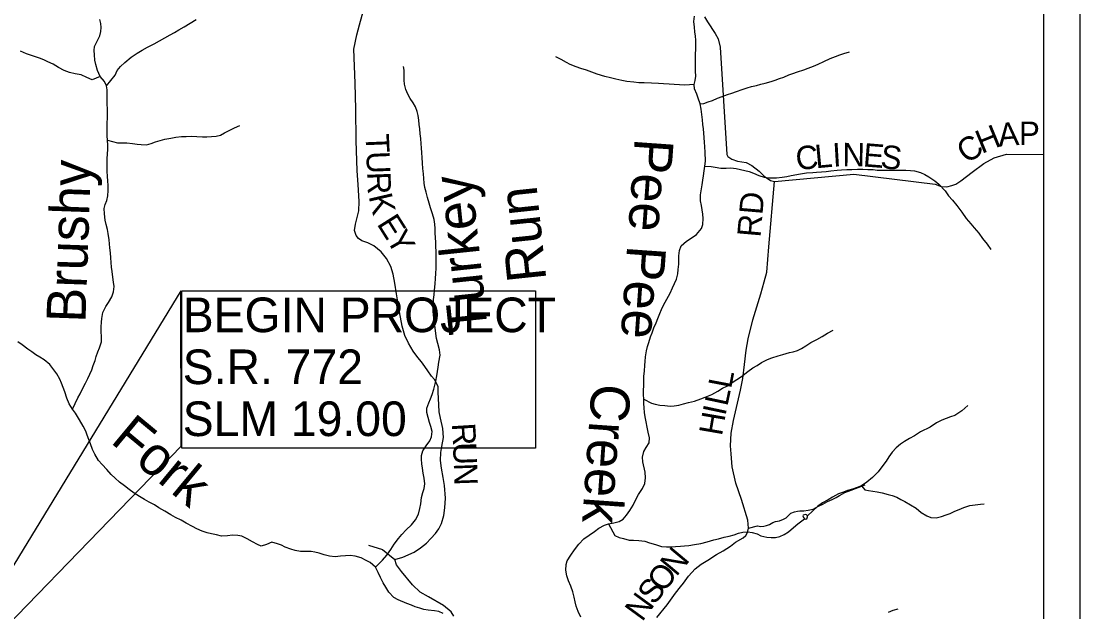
# Model space of a CAD drawing. Extents: x 0 to 34, y 0 to 22.
# Drawn here: x 6.52 to 9.087, y 16.76 to 18.193 of the extents above; entities that cross this region are included whole.
import ezdxf

# ---------------------------------------------------------------- set-up
doc = ezdxf.new("R2010")
doc.units = 0
for name, color, linetype in [('Default', 7, 'Continuous'), ('GM_X_County_Road', 7, 'Continuous'), ('GM_X_County_Road_Text', 7, 'Continuous'), ('GM_X_Minor_Lake', 7, 'Continuous'), ('GM_X_Minor_River', 7, 'Continuous'), ('GM_X_Minor_River_Text', 7, 'Continuous'), ('GM_X_Township_Road', 7, 'Continuous'), ('GM_X_Township_Road_Text', 7, 'Continuous'), ('SH_Cut_Line', 7, 'Continuous'), ('SH_Text', 7, 'Continuous')]:
    doc.layers.add(name, color=color, linetype=linetype)

msp = doc.modelspace()

# ---------------------------------------------------------------- linework, layer by layer
at = {"layer": 'Default'}
msp.add_lwpolyline([(9.087, 13.8822), (2.1062, 13.8822), (2.1062, 20.9054), (9.087, 20.9054)], close=True, dxfattribs=at)
msp.add_lwpolyline([(9, 14), (9, 18.8941), (8.8762, 18.9027), (8.0305, 18.9725), (6.8442, 19.0679), (6.226, 19.1161), (5.8337, 19.1499), (5.3224, 19.1939), (5.1554, 19.2083), (4.831, 19.2363), (4.7661, 18.9124), (5.0018, 18.1008), (4.9996, 18.0806), (4.937, 17.4953), (4.9239, 17.3511), (4.9207, 17.3435), (4.6758, 16.8903), (4.7194, 16.7424)], dxfattribs=at)
at = {"layer": 'GM_X_County_Road'}
for points in [[(8.177, 18.2034), (8.1838, 18.1912), (8.2026, 18.1634), (8.2098, 18.1501), (8.2151, 18.13), (8.2309, 17.8696), (8.2336, 17.8646), (8.243, 17.8585), (8.2571, 17.8532), (8.2779, 17.8497), (8.2916, 17.8425), (8.3097, 17.8291), (8.3215, 17.8173), (8.337, 17.8067), (8.3465, 17.8041), (8.5389, 17.822), (8.7365, 17.7975), (8.751, 17.7918), (8.7642, 17.7913), (8.7768, 17.7943), (8.7866, 17.7977), (8.7984, 17.8057), (8.8258, 17.8264), (8.8543, 17.8476), (8.8794, 17.8616), (8.9094, 17.8706), (9, 17.8699)], [(8.0612, 16.7466), (8.0867, 16.7772), (8.1065, 16.8053), (8.1184, 16.8206), (8.1256, 16.8299), (8.1381, 16.8465), (8.1541, 16.8643), (8.1686, 16.8761), (8.1846, 16.8855), (8.2059, 16.8995), (8.2218, 16.9085), (8.2397, 16.9195), (8.2519, 16.9289), (8.2709, 16.9395), (8.277, 16.9452), (8.2812, 16.9524), (8.2835, 16.9634), (8.282, 16.9824), (8.2662, 17.0329), (8.2531, 17.072), (8.2441, 17.1115), (8.2412, 17.1431), (8.2401, 17.1632), (8.2413, 17.1935), (8.2471, 17.2243), (8.2644, 17.2982), (8.2698, 17.3263), (8.2741, 17.3601), (8.278, 17.395), (8.283, 17.4227), (8.2942, 17.4682), (8.3134, 17.5312), (8.3214, 17.5607), (8.3283, 17.5842), (8.3331, 17.6453), (8.3465, 17.8041)]]:
    msp.add_lwpolyline(points, dxfattribs=at)
at = {"layer": 'GM_X_Minor_Lake'}
for points in [[(8.4245, 16.9957), (8.4222, 16.996), (8.4196, 16.9956), (8.4165, 16.9948), (8.415, 16.9933), (8.4166, 16.9892), (8.4193, 16.9854), (8.4227, 16.9847), (8.4254, 16.9858), (8.4268, 16.9904), (8.4269, 16.9934)], [(8.4269, 16.9934), (8.4245, 16.9957)]]:
    msp.add_lwpolyline(points, dxfattribs=at)
at = {"layer": 'GM_X_Minor_River'}
for points in [[(8.1132, 17.5902), (8.1143, 17.6035), (8.1142, 17.6134), (8.1145, 17.6236), (8.1166, 17.6369), (8.1199, 17.648), (8.1328, 17.6595), (8.1448, 17.6668), (8.1573, 17.6757), (8.1693, 17.6898), (8.1727, 17.6993), (8.1737, 17.7142), (8.1732, 17.7248), (8.1712, 17.735), (8.1692, 17.7456), (8.1672, 17.7574), (8.1675, 17.7714), (8.1696, 17.7866), (8.1711, 17.7961), (8.1729, 17.8072), (8.1743, 17.8174), (8.1761, 17.83), (8.1775, 17.841), (8.1789, 17.8532), (8.1787, 17.8755), (8.1779, 17.8881), (8.177, 17.8994), (8.1753, 17.9214), (8.1744, 17.9321), (8.1732, 17.9423), (8.172, 17.9533), (8.1703, 17.9666), (8.1687, 17.9791), (8.1663, 17.9923), (8.1616, 18.006), (8.1581, 18.0158), (8.1527, 18.029), (8.1515, 18.0389), (8.1544, 18.0492), (8.1558, 18.0594), (8.1554, 18.0719), (8.1552, 18.0879), (8.1547, 18.1012), (8.1554, 18.1126), (8.1557, 18.1251), (8.1559, 18.1357), (8.1558, 18.1471), (8.155, 18.1566), (8.1538, 18.1668), (8.1522, 18.1782), (8.1509, 18.1919), (8.1523, 18.2052)], [(6.6439, 17.2519), (6.6573, 17.279), (6.6629, 17.2893), (6.6677, 17.2996), (6.676, 17.3148), (6.6812, 17.3263), (6.6909, 17.3468), (6.6946, 17.3575), (6.699, 17.3697), (6.702, 17.3796), (6.7057, 17.391), (6.7094, 17.4006), (6.7142, 17.4154), (6.7145, 17.426), (6.714, 17.442), (6.7139, 17.4518), (6.7146, 17.4625), (6.7152, 17.472), (6.7181, 17.4861), (6.7252, 17.5005), (6.7312, 17.5101), (6.7395, 17.5242), (6.7439, 17.5364), (6.7449, 17.5493), (6.7437, 17.5599), (6.7417, 17.5717), (6.7401, 17.5853), (6.7392, 17.5963), (6.7383, 17.6077), (6.7375, 17.6191), (6.7362, 17.6312), (6.735, 17.643), (6.7342, 17.6529), (6.7329, 17.6627), (6.7309, 17.6775), (6.7289, 17.6874), (6.7261, 17.6999), (6.7238, 17.7105), (6.7217, 17.7252), (6.7213, 17.7385), (6.7231, 17.748), (6.7275, 17.7583), (6.7297, 17.7694), (6.7307, 17.7823), (6.7306, 17.7948), (6.7298, 17.8047), (6.7289, 17.8172), (6.7281, 17.8282), (6.7279, 17.8494), (6.7282, 17.8593), (6.7292, 17.8711), (6.7299, 17.8817), (6.7302, 17.892), (6.7289, 17.9045), (6.7281, 17.9144), (6.728, 17.9238), (6.7283, 17.936), (6.7286, 17.9455), (6.7288, 17.9584), (6.7287, 17.9705), (6.729, 17.9804), (6.7285, 17.9914), (6.7281, 18.0032), (6.7283, 18.0168), (6.7279, 18.0263), (6.7263, 18.0358), (6.7216, 18.0464), (6.7116, 18.0588), (6.7047, 18.0732), (6.7007, 18.0879), (6.6987, 18.0982), (6.6975, 18.1114), (6.697, 18.1221), (6.6977, 18.1316), (6.704, 18.1445), (6.7104, 18.1571), (6.7133, 18.1682), (6.714, 18.1777), (6.7132, 18.1871), (6.7108, 18.197)], [(6.7263, 18.0358), (6.7473, 18.0618), (6.7529, 18.0733), (6.7604, 18.0828), (6.7713, 18.0928), (6.7864, 18.1055), (6.8008, 18.1151), (6.8128, 18.1224), (6.8261, 18.1301), (6.8423, 18.1383), (6.8556, 18.1449), (6.868, 18.1522), (6.8809, 18.1599), (6.8915, 18.1657), (6.9017, 18.1715), (6.9153, 18.1792), (6.9296, 18.1877), (6.9443, 18.1973)], [(6.7116, 18.0588), (6.6916, 18.0507), (6.679, 18.0566), (6.6649, 18.0625), (6.6508, 18.0654), (6.6371, 18.0684), (6.6238, 18.0732), (6.6104, 18.0806), (6.5971, 18.0885), (6.5845, 18.0944), (6.5746, 18.0989), (6.5643, 18.103), (6.5445, 18.1096), (6.5323, 18.114), (6.5185, 18.12)], [(8.1515, 18.0389), (8.1295, 18.0379), (8.1162, 18.0382), (8.1036, 18.0392), (8.0915, 18.0398), (8.0774, 18.0408), (8.0656, 18.0415), (8.0481, 18.0424), (8.0303, 18.043), (8.0178, 18.0437), (8.0052, 18.0451), (7.9889, 18.0468), (7.9763, 18.049), (7.9618, 18.0526), (7.9489, 18.0555), (7.9352, 18.0584), (7.9166, 18.0643), (7.9036, 18.0695), (7.891, 18.074), (7.8773, 18.0784), (7.8655, 18.0824), (7.8514, 18.088), (7.8419, 18.0928), (7.8289, 18.0999), (7.8167, 18.1066)], [(8.1663, 17.9923), (8.175, 17.9936), (8.1856, 17.9975), (8.1959, 18.0006), (8.2087, 18.006), (8.2193, 18.0103), (8.2326, 18.015), (8.2432, 18.0185), (8.2542, 18.0224), (8.2682, 18.0271), (8.2803, 18.031), (8.2905, 18.0342), (8.3026, 18.0369), (8.3136, 18.0401), (8.3242, 18.0428), (8.3382, 18.0464), (8.3485, 18.0495), (8.3591, 18.0538), (8.3689, 18.0573), (8.3814, 18.0624), (8.3912, 18.0659), (8.4026, 18.0702), (8.4174, 18.0752), (8.428, 18.0788), (8.4412, 18.0838), (8.4526, 18.0885), (8.4662, 18.0954), (8.4817, 18.1024), (8.4949, 18.1075), (8.5052, 18.1114), (8.5146, 18.1141), (8.5286, 18.1184)], [(7.379, 16.8687), (7.3959, 16.8855), (7.4061, 16.8978), (7.4158, 16.9116), (7.4241, 16.9242), (7.435, 16.9379), (7.4425, 16.9475), (7.4534, 16.959), (7.4662, 16.9713), (7.4764, 16.9831), (7.4831, 16.9972), (7.4864, 17.0109), (7.4889, 17.0223), (7.4907, 17.0372), (7.4936, 17.0497), (7.497, 17.0596), (7.4988, 17.0703), (7.4971, 17.0847), (7.4947, 17.0968), (7.4927, 17.1089), (7.4911, 17.1192), (7.4906, 17.1302), (7.4909, 17.1397), (7.4939, 17.1503), (7.5021, 17.1629), (7.5108, 17.1752), (7.5152, 17.1847), (7.5163, 17.1976), (7.5131, 17.2094), (7.51, 17.2196), (7.5065, 17.2313), (7.5033, 17.2434), (7.5036, 17.2541), (7.5081, 17.267), (7.5122, 17.2765), (7.5166, 17.2872), (7.5207, 17.3005), (7.5233, 17.3101), (7.5251, 17.3199), (7.5276, 17.3325), (7.529, 17.3428), (7.5308, 17.3538), (7.533, 17.3656), (7.5355, 17.3831), (7.5339, 17.396), (7.53, 17.4107), (7.5272, 17.4232), (7.5256, 17.4354), (7.5236, 17.4494), (7.5223, 17.4592), (7.5207, 17.4737), (7.519, 17.4884), (7.5189, 17.5021), (7.5195, 17.5177), (7.521, 17.5291), (7.522, 17.5401), (7.5234, 17.5557), (7.5244, 17.569), (7.5254, 17.5811), (7.5261, 17.594), (7.526, 17.605), (7.5262, 17.6218), (7.5261, 17.6343), (7.5256, 17.646), (7.5252, 17.6563), (7.5243, 17.6684), (7.5238, 17.6787), (7.5237, 17.6904), (7.5229, 17.7007), (7.5213, 17.7117), (7.517, 17.7257), (7.5127, 17.7401), (7.5095, 17.7514), (7.5048, 17.765), (7.5017, 17.7779), (7.4989, 17.7893), (7.4973, 17.8003), (7.4961, 17.8109), (7.4952, 17.823), (7.494, 17.8352), (7.4931, 17.8484), (7.4922, 17.8621), (7.4917, 17.8739), (7.4909, 17.886), (7.49, 17.8955), (7.4888, 17.9084), (7.4875, 17.9198), (7.4863, 17.9315), (7.4851, 17.9425), (7.4838, 17.9527), (7.4822, 17.9637), (7.4802, 17.9736), (7.4763, 17.9853), (7.4702, 17.9951), (7.4629, 18.0053), (7.4575, 18.0155), (7.4524, 18.0268), (7.4493, 18.0405), (7.4484, 18.05), (7.4487, 18.0621), (7.4482, 18.0739)], [(7.4482, 18.0739), (7.4466, 18.0833)], [(6.7289, 17.9045), (6.7533, 17.8975), (6.7658, 17.8976), (6.7757, 17.8981), (6.7894, 17.8963), (6.8012, 17.8946), (6.8107, 17.8939), (6.824, 17.8933), (6.8353, 17.896), (6.8459, 17.8999), (6.8569, 17.9038), (6.8683, 17.9066), (6.8823, 17.909), (6.8952, 17.9114), (6.9085, 17.913), (6.9202, 17.9135), (6.9339, 17.9137), (6.9461, 17.913), (6.9594, 17.9124), (6.97, 17.9125), (6.981, 17.913), (6.9928, 17.9142), (7.003, 17.9166), (7.0132, 17.9224), (7.0374, 17.934), (7.0499, 17.9395)], [(8.1775, 17.841), (8.1927, 17.8404), (8.203, 17.839), (8.2163, 17.836), (8.2292, 17.8366), (8.241, 17.837), (8.2535, 17.8356), (8.2638, 17.8335), (8.2744, 17.8309), (8.2851, 17.828), (8.2954, 17.8239), (8.3087, 17.8183), (8.3213, 17.8147), (8.3335, 17.8125), (8.3517, 17.8127), (8.365, 17.8147), (8.3767, 17.816), (8.3873, 17.8183), (8.4093, 17.8223), (8.4245, 17.8248), (8.4393, 17.8261), (8.4488, 17.8265), (8.4602, 17.8274), (8.4716, 17.8286), (8.4833, 17.8299), (8.4989, 17.8312), (8.5087, 17.832), (8.522, 17.8329), (8.5342, 17.833), (8.5482, 17.8336), (8.5611, 17.8337), (8.5733, 17.8334), (8.5858, 17.8328), (8.5953, 17.8317), (8.6063, 17.8315), (8.6177, 17.8312), (8.6546, 17.8315), (8.6648, 17.8313), (8.6766, 17.831), (8.6865, 17.83), (8.701, 17.8259), (8.7109, 17.8211), (8.7212, 17.8151), (8.7353, 17.8054), (8.7449, 17.7975), (8.7602, 17.7813), (8.7683, 17.7696), (8.7786, 17.7587), (8.7886, 17.7459), (8.8009, 17.7293), (8.8113, 17.7142), (8.8228, 17.7015), (8.8305, 17.6913), (8.842, 17.6785), (8.8508, 17.666), (8.8627, 17.6517), (8.8712, 17.6393)], [(7.8772, 16.7474), (7.8706, 16.7607), (7.8659, 16.7739), (7.8632, 16.7841), (7.8608, 16.7959), (7.8576, 16.8088), (7.8526, 16.8224), (7.8472, 16.8356), (7.8432, 16.8477), (7.8405, 16.8614), (7.8411, 16.8746), (7.8441, 16.8842), (7.8527, 16.8979), (7.8617, 16.9109), (7.8722, 16.9243), (7.8846, 16.9369), (7.8975, 16.9462), (7.9099, 16.9554), (7.9209, 16.9631), (7.9345, 16.9701), (7.9443, 16.9736), (7.9572, 16.976), (7.9697, 16.9795), (7.9795, 16.9846), (7.9874, 16.9945), (7.9957, 17.0063), (8.0035, 17.0186), (8.0095, 17.0312), (8.017, 17.0449), (8.0267, 17.059), (8.0323, 17.0712), (8.0341, 17.0853), (8.0328, 17.0986), (8.0273, 17.1243), (8.0268, 17.1353), (8.0297, 17.149), (8.035, 17.159), (8.0425, 17.17), (8.0435, 17.1822), (8.0403, 17.1958), (8.038, 17.208), (8.0352, 17.2208), (8.0332, 17.2333), (8.0316, 17.2436), (8.0303, 17.255), (8.0299, 17.2656), (8.0294, 17.2758), (8.0289, 17.2872), (8.0292, 17.2975), (8.0295, 17.3081), (8.0298, 17.3191), (8.03, 17.3316), (8.0311, 17.3442), (8.0321, 17.3582), (8.0328, 17.3677), (8.0338, 17.3788), (8.0363, 17.3932), (8.0389, 17.4039), (8.0415, 17.4134), (8.0459, 17.4275), (8.0496, 17.437), (8.0541, 17.4488), (8.0593, 17.4614), (8.0634, 17.4717), (8.0682, 17.4842), (8.0723, 17.4938), (8.0775, 17.5041), (8.0854, 17.5189), (8.0932, 17.5331), (8.0992, 17.546), (8.1089, 17.5674), (8.1122, 17.5803), (8.1132, 17.5902)], [(8.0294, 17.2758), (8.0481, 17.2665), (8.0576, 17.2636), (8.0686, 17.2618), (8.0808, 17.2604), (8.0937, 17.2594), (8.1032, 17.2598), (8.115, 17.2618), (8.1259, 17.265), (8.1377, 17.2678), (8.1525, 17.2713), (8.168, 17.2768), (8.1782, 17.2807), (8.1949, 17.2877), (8.2089, 17.2954), (8.2209, 17.3024), (8.2312, 17.3078), (8.2436, 17.3162), (8.2663, 17.3309), (8.2821, 17.3432), (8.2942, 17.3517), (8.3044, 17.3578), (8.315, 17.3648), (8.3297, 17.3721), (8.3403, 17.3764), (8.3551, 17.3815), (8.3668, 17.3846), (8.3827, 17.3889), (8.3922, 17.3909), (8.4021, 17.3941), (8.4123, 17.3987), (8.4228, 17.4057), (8.4349, 17.4134), (8.4493, 17.4211), (8.4618, 17.4284), (8.475, 17.4358), (8.489, 17.4435)], [(7.3565, 16.8848), (7.3439, 16.8915), (7.3298, 16.8955), (7.3172, 16.8969), (7.3066, 16.8961), (7.2945, 16.8948), (7.2812, 16.8936), (7.2671, 16.8949), (7.2542, 16.8986), (7.242, 16.9023), (7.2321, 16.9049), (7.2226, 16.9063), (7.1975, 16.9068), (7.1846, 16.9086), (7.1739, 16.9119), (7.1602, 16.9174), (7.1507, 16.9215), (7.1412, 16.9252), (7.1275, 16.9289), (7.115, 16.9238), (7.1021, 16.9195), (7.0926, 16.9233), (7.0804, 16.93), (7.0681, 16.9374), (7.0552, 16.9438), (7.0453, 16.9452), (7.0324, 16.9462), (7.0198, 16.9449), (7.0058, 16.9441), (6.9936, 16.9466), (6.9814, 16.9495), (6.9704, 16.9521), (6.959, 16.9561), (6.946, 16.9613), (6.9353, 16.9669), (6.9201, 16.9755), (6.9079, 16.9822), (6.8937, 16.9893), (6.8823, 16.9956), (6.8678, 17.0042), (6.8537, 17.0128), (6.843, 17.0196), (6.8304, 17.0263), (6.8189, 17.0326), (6.8067, 17.0401), (6.7941, 17.0483), (6.7819, 17.0565), (6.77, 17.0655), (6.7582, 17.0749), (6.7475, 17.0843), (6.7379, 17.0933), (6.7275, 17.1054), (6.716, 17.1174), (6.7076, 17.1276), (6.698, 17.1427), (6.6926, 17.1536), (6.6879, 17.1676), (6.684, 17.1778), (6.6801, 17.1884), (6.6762, 17.1987), (6.6704, 17.2104), (6.6616, 17.2258), (6.6515, 17.2421), (6.6439, 17.2519), (6.6361, 17.2651), (6.6307, 17.2787), (6.6256, 17.2935), (6.6217, 17.3044), (6.6179, 17.3146), (6.6132, 17.3248), (6.6063, 17.3377), (6.5993, 17.3475), (6.589, 17.3599), (6.5752, 17.3712), (6.5649, 17.3779), (6.5554, 17.3835), (6.5454, 17.3906), (6.5359, 17.3977), (6.5221, 17.4082), (6.5118, 17.4154)], [(8.8153, 17.2606), (8.8006, 17.2476), (8.7836, 17.2368), (8.7734, 17.2333), (8.7627, 17.2294), (8.7522, 17.2251), (8.7397, 17.2189), (8.7238, 17.2085), (8.7004, 17.1965), (8.6864, 17.1873), (8.6739, 17.1803), (8.6622, 17.1734), (8.652, 17.1668), (8.6415, 17.1576), (8.6321, 17.1473), (8.6238, 17.1358), (8.6171, 17.1259), (8.6096, 17.1155), (8.5979, 17.0995), (8.5844, 17.0857), (8.5708, 17.0749), (8.5572, 17.0657), (8.547, 17.0614), (8.536, 17.0579), (8.5239, 17.0543), (8.514, 17.0508), (8.5019, 17.0462), (8.4876, 17.0384), (8.477, 17.0315), (8.4634, 17.0245), (8.4505, 17.0153), (8.4269, 16.9934)], [(8.5572, 17.0657), (8.5653, 17.0563), (8.5748, 17.0548), (8.5854, 17.053), (8.5953, 17.0512), (8.6079, 17.0487), (8.6219, 17.0447), (8.6322, 17.0425), (8.6433, 17.038), (8.6532, 17.0328), (8.6627, 17.0276), (8.6765, 17.0201), (8.6898, 17.0115), (8.7021, 17.0014), (8.7158, 16.9928), (8.7257, 16.9887), (8.7386, 16.9885), (8.7519, 16.9916), (8.7629, 16.9952), (8.7727, 16.999), (8.7841, 17.0041), (8.7943, 17.0084), (8.8057, 17.013), (8.8204, 17.0177), (8.8329, 17.0198), (8.8458, 17.0214), (8.8553, 17.0219)], [(7.9443, 16.9736), (7.9597, 16.9456), (7.9697, 16.9408), (7.9803, 16.9382), (7.9944, 16.9342), (8.0047, 16.9339), (8.0172, 16.9329), (8.032, 16.9312), (8.0438, 16.9278), (8.0583, 16.9231), (8.0724, 16.919), (8.0845, 16.9176), (8.0948, 16.9181), (8.1062, 16.9186), (8.1183, 16.9198), (8.1282, 16.9203), (8.1392, 16.9212), (8.1529, 16.9232), (8.1676, 16.926), (8.1832, 16.9296), (8.1998, 16.9347), (8.2112, 16.9371), (8.2249, 16.941), (8.2366, 16.9438), (8.2491, 16.9473), (8.259, 16.9508), (8.2699, 16.9532), (8.2817, 16.9544), (8.2927, 16.953), (8.3042, 16.9493), (8.3137, 16.9449), (8.3282, 16.9412), (8.3384, 16.9406), (8.349, 16.9407), (8.3593, 16.9427), (8.3702, 16.9477), (8.3808, 16.9543), (8.3929, 16.965), (8.4031, 16.9738), (8.4193, 16.9854)], [(7.5429, 16.756), (7.5322, 16.7612), (7.522, 16.7626), (7.5071, 16.7644), (7.4965, 16.7662), (7.4862, 16.7691), (7.4755, 16.772), (7.466, 16.7761), (7.455, 16.7802), (7.4336, 16.7891), (7.4233, 16.7951), (7.4114, 16.8075), (7.4037, 16.8203), (7.3979, 16.8305), (7.3914, 16.8437), (7.3856, 16.8558), (7.379, 16.8687), (7.3664, 16.8799), (7.3565, 16.8848)], [(8.6229, 16.7592), (8.6343, 16.7639), (8.6468, 16.7674)]]:
    msp.add_lwpolyline(points, dxfattribs=at)
at = {"layer": 'GM_X_Township_Road'}
for points in [[(7.5689, 16.7495), (7.5623, 16.7603), (7.5437, 16.7752), (7.5077, 16.7968), (7.4874, 16.8082), (7.4688, 16.8256), (7.4424, 16.858), (7.4298, 16.8742), (7.4256, 16.8868), (7.4454, 16.8927), (7.4731, 16.9047), (7.4883, 16.9153), (7.5024, 16.9266), (7.5135, 16.938), (7.5249, 16.9501), (7.5329, 16.9611), (7.539, 16.9747), (7.5444, 16.9941), (7.5475, 17.0127), (7.5487, 17.0358), (7.5461, 17.0662), (7.5428, 17.0863), (7.5394, 17.1087), (7.5368, 17.1273), (7.5376, 17.1463), (7.5396, 17.1615), (7.5438, 17.1827), (7.542, 17.2048), (7.5368, 17.2302), (7.5338, 17.2454), (7.5327, 17.2625), (7.5313, 17.2929), (7.5313, 17.3069), (7.5219, 17.324), (7.5151, 17.332), (7.5056, 17.3449), (7.4928, 17.3632), (7.4792, 17.3803), (7.4701, 17.3925), (7.4592, 17.4115), (7.4505, 17.4301), (7.4434, 17.4533), (7.437, 17.4879), (7.4299, 17.5312), (7.4255, 17.557), (7.4218, 17.579), (7.4161, 17.598), (7.4059, 17.617), (7.3931, 17.6338), (7.3753, 17.6479), (7.3601, 17.6551), (7.3457, 17.6601), (7.3374, 17.6658), (7.3321, 17.673), (7.328, 17.6848), (7.3307, 17.7007), (7.3349, 17.7163), (7.3388, 17.733), (7.3392, 17.7558), (7.3367, 17.7971), (7.3345, 17.8302), (7.3325, 17.9034), (7.3316, 17.9793), (7.3299, 18.0427), (7.3263, 18.1247), (7.3334, 18.1599), (7.3405, 18.1844), (7.3528, 18.2312)], [(8.3792, 16.9921), (8.3807, 16.9935), (8.3864, 16.9995), (8.3948, 17.0025), (8.402, 17.004), (8.4081, 17.0048), (8.4179, 17.0055), (8.4282, 17.0066), (8.4403, 17.0088), (8.4533, 17.0164), (8.4639, 17.0213), (8.4749, 17.0277), (8.4863, 17.0323), (8.4958, 17.0375), (8.5042, 17.0421), (8.5171, 17.05), (8.5262, 17.0526), (8.5661, 17.0685)], [(8.2835, 16.9634), (8.3055, 16.9686), (8.3135, 16.9675), (8.3207, 16.9682), (8.3268, 16.9693), (8.3344, 16.9724), (8.3423, 16.9765), (8.3488, 16.9791), (8.3587, 16.981), (8.3682, 16.9848), (8.3746, 16.9882), (8.3792, 16.9921)], [(7.3624, 16.9219), (7.3962, 16.9111), (7.4256, 16.8868)]]:
    msp.add_lwpolyline(points, dxfattribs=at)
at = {"layer": 'SH_Cut_Line'}
msp.add_lwpolyline([(2.2, 19.4329), (2.2, 14), (9, 14), (9, 18.8941), (8.8762, 18.9027), (8.0305, 18.9725), (6.8442, 19.0679), (6.226, 19.1161), (5.8337, 19.1499), (5.3224, 19.1939), (5.1554, 19.2083), (4.831, 19.2363), (4.7641, 19.2419), (3.1893, 19.3592), (2.7961, 19.3885)], close=True, dxfattribs=at)
at = {"layer": 'SH_Text'}
for points in [[(6.2851, 16.5198), (6.9075, 17.1619), (6.9066, 17.5389)], [(6.9096, 17.5388), (7.7667, 17.5388), (7.7667, 17.1575), (6.9096, 17.1575)]]:
    msp.add_lwpolyline(points, close=True, dxfattribs=at)

# ---------------------------------------------------------------- texts
at = {"layer": 'GM_X_County_Road_Text'}
for s, height, rotation, p in [('A', 0.0568, 4.6717, (8.8908, 17.8885)), ('P', 0.0568, 359.8907, (8.9394, 17.8925)), ('H', 0.0568, 22.2749, (8.849, 17.8706)), ('I', 0.0568, 3.3804, (8.4888, 17.8398)), ('N', 0.0568, 359.3883, (8.511, 17.8411)), ('E', 0.0568, 355.3963, (8.56, 17.8407)), ('C', 0.0568, 35.4537, (8.814, 17.8452)), ('C', 0.0568, 5.3764, (8.4005, 17.8315)), ('L', 0.0568, 5.3764, (8.447, 17.8359)), ('S', 0.0568, 353.4002, (8.6018, 17.8373)), ('RD', 0.05682, 85.0738, (8.3126, 17.6673)), ('L', 0.0568, 79.1742, (8.2413, 17.2997)), ('L', 0.0568, 78.0243, (8.2322, 17.2569)), ('I', 0.0568, 78.0012, (8.2274, 17.234)), ('H', 0.0568, 80.1897, (8.219, 17.1853)), ('N', 0.0568, 50.0475, (8.1083, 16.8439)), ('O', 0.0568, 52.4496, (8.0783, 16.8048)), ('S', 0.0568, 52.5172, (8.0549, 16.7744)), ('N', 0.0568, 53.8208, (8.0256, 16.7343))]:
    msp.add_text(s, height=height, rotation=rotation, dxfattribs=at).set_placement(p)
at = {"layer": 'GM_X_Minor_River_Text'}
for s, height, rotation, p in [('Pee Pee', 0.0947, 265.9803, (8.0078, 17.9103)), ('Brushy', 0.0947, 88, (6.6755, 17.4607)), ('Turkey', 0.0947, 95.9992, (7.6521, 17.4385)), ('Run', 0.0947, 95.9994, (7.7936, 17.5653)), ('Creek', 0.09471, 265.9801, (7.9038, 17.3152)), ('Fork', 0.0947, 320.299, (6.7338, 17.1719))]:
    msp.add_text(s, height=height, rotation=rotation, dxfattribs=at).set_placement(p)
at = {"layer": 'GM_X_Township_Road_Text'}
for s, rotation, p in [('T', 272.3492, (7.3547, 17.9188)), ('U', 272.3488, (7.3565, 17.8764)), ('R', 272.3307, (7.3585, 17.8264)), ('K', 283.1632, (7.362, 17.7684)), ('E', 302.185, (7.3811, 17.7011)), ('Y', 299.8773, (7.4034, 17.6656)), ('R', 273.6048, (7.5638, 17.2166)), ('U', 272.2336, (7.5667, 17.1703)), ('N', 272.0769, (7.5687, 17.1204))]:
    msp.add_text(s, height=0.0568, rotation=rotation, dxfattribs=at).set_placement(p)
at = {"layer": 'SH_Text'}
for s, p in [('BEGIN PROJECT', (6.9116, 17.4385)), ('S.R. 772             ', (6.9116, 17.3125)), ('SLM 19.00         ', (6.9116, 17.1865))]:
    msp.add_text(s, height=0.084, dxfattribs=at).set_placement(p)

doc.saveas('drawing.dxf')
